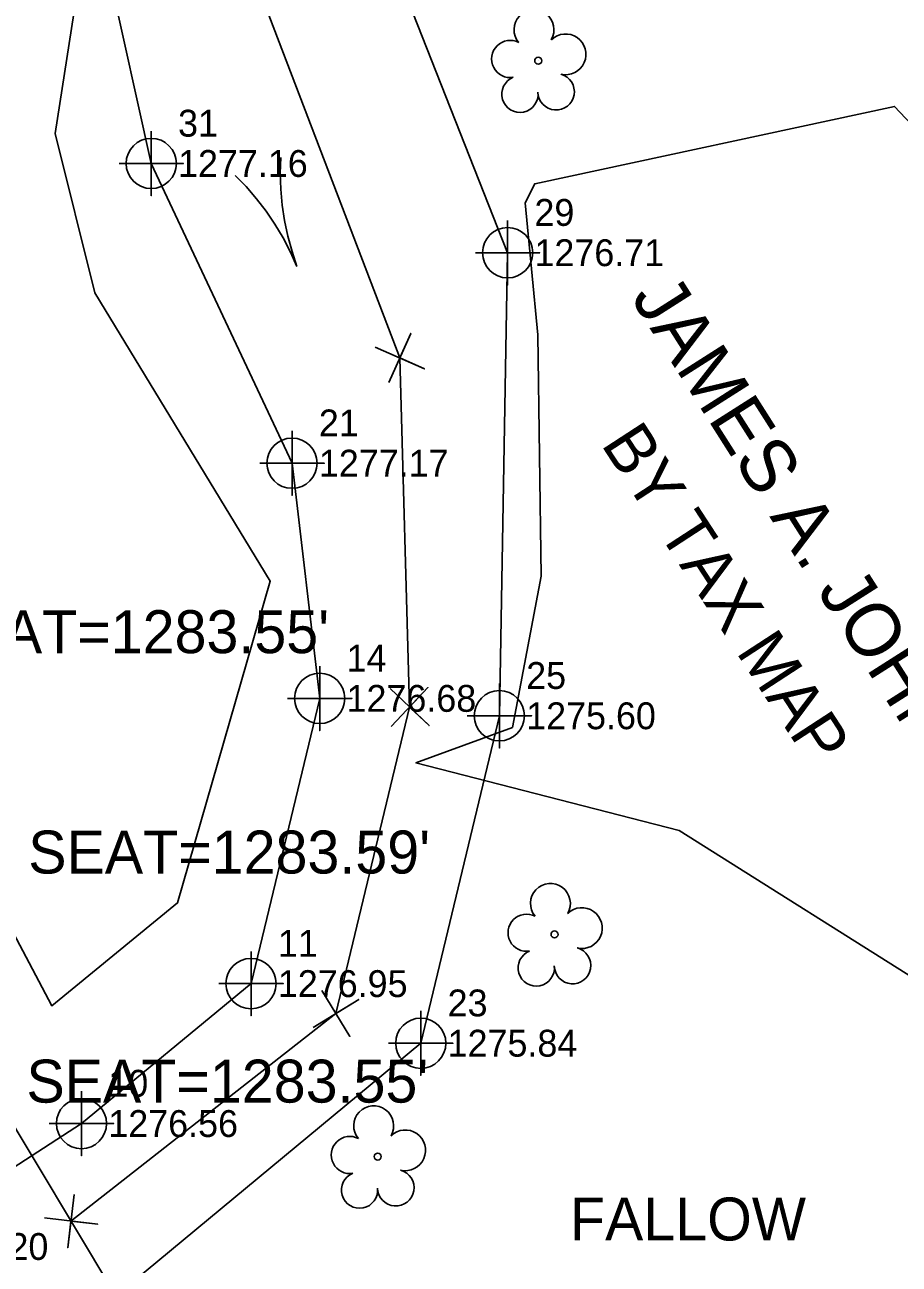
# Model space of a CAD drawing. Extents: x 1393723 to 1394549, y 957573 to 958412.
# Drawn here: x 1394233.6 to 1394315.1, y 958102.9 to 958218.3 of the extents above; entities that cross this region are included whole.
import ezdxf

# ---------------------------------------------------------------- set-up
doc = ezdxf.new("R2010")
doc.units = 0
for name, color, linetype in [('Exist Hydro Jurisdictional Stream or Body of Water', 7, 'Continuous'), ('Exist Hydro Stream Flow Arrow CELL', 7, 'Continuous'), ('Exist Hydro Stream or Body of Water Cogo Elevation', 7, 'Continuous'), ('Exist Hydro Stream or Body of Water Cogo Number', 7, 'Continuous'), ('Exist Hydro Stream or Body of Water Cogo Point CELL', 7, 'Continuous'), ('Exist Property Corner CELL', 7, 'Continuous'), ('Exist Property Deed Book Text', 7, 'Continuous'), ('Exist Property Line', 7, 'Continuous'), ('Exist Property Line Text', 7, 'Continuous'), ('Exist Property Owner Text', 7, 'Continuous'), ('Exist Right of Way Line', 7, 'Continuous'), ('Exist Structure Major Bridge Seat Top Elevation', 7, 'Continuous'), ('Exist Vegetation Tree CELL', 7, 'Continuous'), ('Exist Vegetation Woods Line', 7, 'Continuous'), ('Exist Vegetation Woods Line Text', 7, 'Continuous')]:
    doc.layers.add(name, color=color, linetype=linetype)

msp = doc.modelspace()

# ---------------------------------------------------------------- linework, layer by layer
at = {"layer": 'Exist Hydro Jurisdictional Stream or Body of Water'}
for points in [[(1394173.56, 958323.84), (1394160.39, 958316.41), (1394154.66, 958297.46), (1394149.27, 958283.15), (1394155.87, 958264.15), (1394168.98, 958246.06), (1394177.42, 958243.2), (1394198.48, 958248.51), (1394226.11, 958259.88), (1394245.4, 958262.42), (1394251.97, 958257.71), (1394253.55, 958252.43), (1394246.6, 958237.67), (1394241.52, 958222.95), (1394245.4, 958205.43), (1394258.52, 958177.52), (1394261.1, 958155.62), (1394254.7, 958129.06), (1394238.9, 958116.03), (1394219.59, 958103.52)], [(1394182.65, 958307.54), (1394169.76, 958290.8), (1394172.1, 958270.66), (1394177.6, 958260.63), (1394210.23, 958270.05), (1394243.43, 958275.21), (1394265.63, 958269.83), (1394275.6, 958257.19), (1394267.1, 958226.25), (1394278.61, 958197.12), (1394277.84, 958154), (1394270.52, 958123.51), (1394228.57, 958088.78)]]:
    msp.add_lwpolyline(points, dxfattribs=at)
at = {"layer": 'Exist Hydro Stream Flow Arrow CELL'}
msp.add_line((1394257.16, 958200.5), (1394257.16, 958200.5), dxfattribs=at)
for points in [[(1394257.47, 958205.99), (1394257.4, 958204.52), (1394257.48, 958203.03), (1394257.59, 958201.55), (1394257.82, 958200.12), (1394258.13, 958198.67), (1394258.52, 958197.23), (1394258.98, 958195.84)], [(1394253.21, 958204.32), (1394254.25, 958203.29), (1394255.2, 958202.13), (1394256.12, 958200.98), (1394256.93, 958199.78), (1394257.68, 958198.5), (1394258.38, 958197.17), (1394258.98, 958195.84)]]:
    msp.add_lwpolyline(points, dxfattribs=at)
at = {"layer": 'Exist Hydro Stream or Body of Water Cogo Point CELL'}
for points in [[(1394242.4, 958205.43), (1394248.4, 958205.43), (1394245.4, 958205.43), (1394245.4, 958202.43), (1394245.4, 958208.43)], [(1394275.61, 958197.12), (1394281.61, 958197.12), (1394278.61, 958197.12), (1394278.61, 958194.12), (1394278.61, 958200.12)], [(1394255.52, 958177.52), (1394261.52, 958177.52), (1394258.52, 958177.52), (1394258.52, 958174.52), (1394258.52, 958180.52)], [(1394258.1, 958155.62), (1394264.1, 958155.62), (1394261.1, 958155.62), (1394261.1, 958152.62), (1394261.1, 958158.62)], [(1394274.84, 958154), (1394280.84, 958154), (1394277.84, 958154), (1394277.84, 958151), (1394277.84, 958157)], [(1394251.7, 958129.06), (1394257.7, 958129.06), (1394254.7, 958129.06), (1394254.7, 958126.06), (1394254.7, 958132.06)], [(1394267.52, 958123.51), (1394273.52, 958123.51), (1394270.52, 958123.51), (1394270.52, 958120.51), (1394270.52, 958126.51)], [(1394235.9, 958116.03), (1394241.9, 958116.03), (1394238.9, 958116.03), (1394238.9, 958113.03), (1394238.9, 958119.03)]]:
    msp.add_lwpolyline(points, dxfattribs=at)
for centre in [(1394245.4, 958205.43), (1394278.61, 958197.12), (1394258.52, 958177.52), (1394261.1, 958155.62), (1394277.84, 958154), (1394254.7, 958129.06), (1394270.52, 958123.51), (1394238.9, 958116.03)]:
    msp.add_circle(centre, 2.34, dxfattribs=at)
at = {"layer": 'Exist Property Corner CELL'}
for p, q in [((1394268.57, 958187.32), (1394268.57, 958187.32)), ((1394269.47, 958154.81), (1394269.47, 958154.81)), ((1394262.61, 958126.28), (1394262.61, 958126.28)), ((1394237.92, 958106.95), (1394237.92, 958106.95))]:
    msp.add_line(p, q, dxfattribs=at)
for points in [[(1394266.28, 958188.34), (1394270.85, 958186.3), (1394268.57, 958187.32), (1394269.58, 958189.6), (1394267.55, 958185.04)], [(1394267.65, 958156.53), (1394271.29, 958153.09), (1394269.47, 958154.81), (1394271.19, 958156.63), (1394267.75, 958153)], [(1394261.3, 958128.42), (1394263.91, 958124.15), (1394262.61, 958126.28), (1394264.74, 958127.59), (1394260.48, 958124.98)], [(1394238.23, 958109.43), (1394237.62, 958104.47), (1394237.92, 958106.95), (1394240.41, 958106.65), (1394235.44, 958107.25)]]:
    msp.add_lwpolyline(points, dxfattribs=at)
at = {"layer": 'Exist Property Line'}
for p, q in [((1394254.31, 958224.6), (1394268.57, 958187.32)), ((1394268.57, 958187.32), (1394269.47, 958154.81)), ((1394269.47, 958154.81), (1394262.61, 958126.28)), ((1394262.61, 958126.28), (1394237.92, 958106.95))]:
    msp.add_line(p, q, dxfattribs=at)
at = {"layer": 'Exist Right of Way Line'}
msp.add_line((1394208.88, 958155.31), (1394253.08, 958081.72), dxfattribs=at)
at = {"layer": 'Exist Vegetation Tree CELL'}
for p, q in [((1394281.46, 958215), (1394281.46, 958215)), ((1394282.98, 958133.64), (1394282.98, 958133.64)), ((1394266.51, 958112.95), (1394266.51, 958112.95))]:
    msp.add_line(p, q, dxfattribs=at)
for centre in [(1394281.46, 958215), (1394282.98, 958133.64), (1394266.51, 958112.95)]:
    msp.add_circle(centre, 0.326, dxfattribs=at)
for centre, radius, start, end in [((1394281.07, 958217.88), 1.86, 330.1651, 219.7134), ((1394278.85, 958215.16), 1.73, 62.6636, 279.3457), ((1394284.01, 958215.59), 1.9, 257.1011, 134.1999), ((1394279.76, 958211.88), 1.69, 111.5671, 6.231), ((1394283.13, 958212.11), 1.7, 181.2822, 74.56), ((1394282.6, 958136.52), 1.86, 330.1651, 219.7134), ((1394285.53, 958134.23), 1.9, 257.1011, 134.1999), ((1394280.38, 958133.8), 1.73, 62.6636, 279.3457), ((1394284.66, 958130.74), 1.7, 181.2822, 74.56), ((1394281.28, 958130.52), 1.69, 111.5671, 6.231), ((1394266.13, 958115.82), 1.86, 330.1651, 219.7134), ((1394263.91, 958113.1), 1.73, 62.6636, 279.3457), ((1394269.06, 958113.53), 1.9, 257.1011, 134.1999), ((1394264.81, 958109.83), 1.69, 111.5671, 6.231), ((1394268.19, 958110.05), 1.7, 181.2822, 74.56)]:
    msp.add_arc(centre, radius, start, end, dxfattribs=at)
at = {"layer": 'Exist Vegetation Woods Line'}
for points in [[(1394224.39, 958146.28), (1394171.35, 958236.02), (1394198.19, 958242.19), (1394237.06, 958251.15), (1394240.14, 958232), (1394236.44, 958208.22), (1394240.14, 958193.4), (1394256.49, 958166.53), (1394247.86, 958136.58), (1394236.13, 958127), (1394225.03, 958148)], [(1394318.85, 958128.04), (1394294.61, 958143.32), (1394270.07, 958149.61), (1394279.05, 958152.91), (1394281.74, 958166.99), (1394281.44, 958189.46), (1394280.24, 958201.75), (1394281.14, 958203.54), (1394314.66, 958210.74), (1394325.14, 958199.65), (1394331.73, 958181.97), (1394338.01, 958165.79), (1394347.29, 958148.41), (1394360.76, 958143.62), (1394316.46, 958128.63)]]:
    msp.add_lwpolyline(points, dxfattribs=at)

# ---------------------------------------------------------------- texts
at = {"layer": 'Exist Hydro Stream or Body of Water Cogo Elevation'}
for s, p in [('1277.16', (1394247.9, 958204.18)), ('1276.71', (1394281.11, 958195.87)), ('1277.17', (1394261.02, 958176.27)), ('1276.68', (1394263.6, 958154.37)), ('1275.60', (1394280.34, 958152.75)), ('1276.95', (1394257.2, 958127.81)), ('1275.84', (1394273.02, 958122.26)), ('1276.56', (1394241.4, 958114.78)), ('1276.20', (1394223.73, 958103.33))]:
    msp.add_text(s, height=2.5, dxfattribs=at).set_placement(p)
at = {"layer": 'Exist Hydro Stream or Body of Water Cogo Number'}
for s, p in [('31', (1394247.9, 958207.93)), ('29', (1394281.11, 958199.62)), ('21', (1394261.02, 958180.02)), ('14', (1394263.6, 958158.12)), ('25', (1394280.34, 958156.5)), ('11', (1394257.2, 958131.56)), ('23', (1394273.02, 958126.01)), ('10', (1394241.4, 958118.53))]:
    msp.add_text(s, height=2.5, dxfattribs=at).set_placement(p)
at = {"layer": 'Exist Property Deed Book Text'}
msp.add_text('BY TAX MAP', height=4.5, rotation=303.057, dxfattribs=at).set_placement((1394287.25, 958179.3))
at = {"layer": 'Exist Property Line Text'}
msp.add_text('CENTERLINE OF CREEK = PROPERTY LINE', height=4, rotation=297.0845, dxfattribs=at).set_placement((1394296.44, 958278.54))
at = {"layer": 'Exist Property Owner Text'}
msp.add_text('JAMES A. JOHNSON', height=5, rotation=302.4612, dxfattribs=at).set_placement((1394290.02, 958192.94))
at = {"layer": 'Exist Structure Major Bridge Seat Top Elevation'}
for s, p in [("SEAT=1283.55'", (1394224.53, 958159.83)), ("SEAT=1283.59'", (1394233.94, 958139.31)), ("SEAT=1283.55'", (1394233.77, 958117.98))]:
    msp.add_text(s, height=4, dxfattribs=at).set_placement(p)
at = {"layer": 'Exist Vegetation Woods Line Text'}
msp.add_text('FALLOW', height=4, dxfattribs=at).set_placement((1394284.42, 958105.14))

doc.saveas('drawing.dxf')
